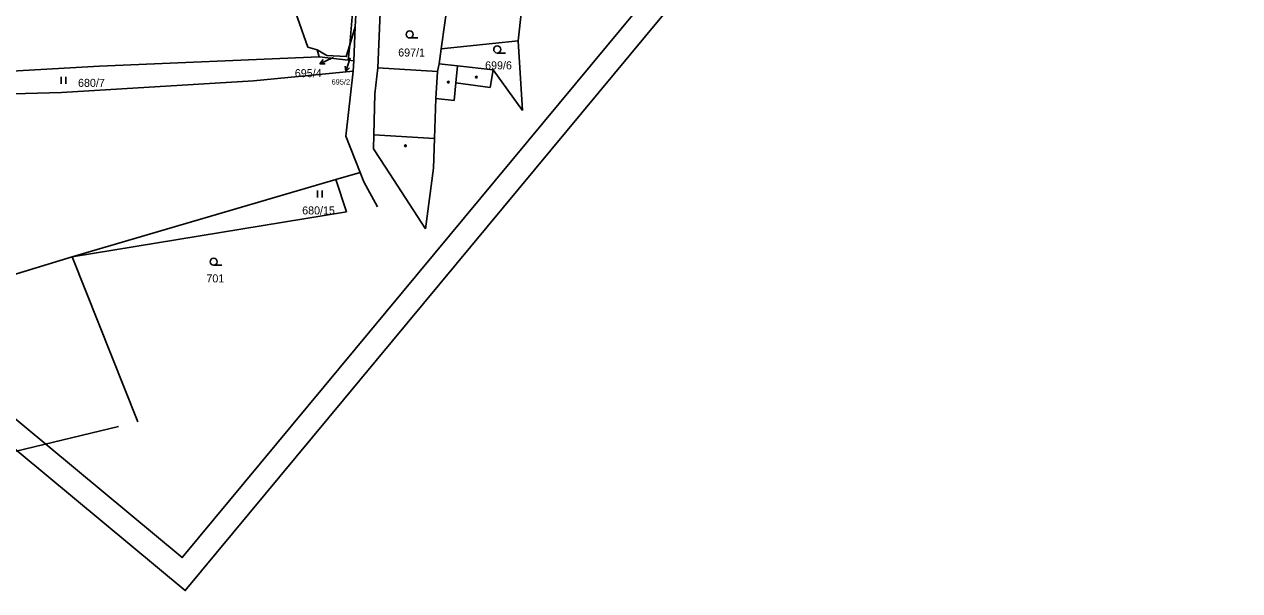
# Model space of a CAD drawing. Extents: x -738085 to -734306, y -1122197 to -1119753.
# Drawn here: x -737792.2 to -737534.1, y -1122100.7 to -1121980.5 of the extents above; entities that cross this region are included whole.
import ezdxf

# ---------------------------------------------------------------- set-up
doc = ezdxf.new("R2010")
doc.units = 0
for name, color, linetype in [('Hranice parcel', 7, 'Continuous'), ('Parcelní čísla', 7, 'Continuous'), ('Pop  PČ popisy', 7, 'Continuous'), ('Vnitřní kresba', 7, 'Continuous'), ('Vrstva 1', 7, 'Continuous'), ('Značky budov', 7, 'Continuous'), ('Značky kultur', 7, 'Continuous')]:
    doc.layers.add(name, color=color, linetype=linetype)

msp = doc.modelspace()

# ---------------------------------------------------------------- linework, layer by layer
at = {"layer": 'Hranice parcel'}
for p, q in [((-737723.1, -1121984.84), (-737719.99, -1121949.35)), ((-737719.99, -1121949.35), (-737721.96, -1121981)), ((-737698.78, -1121951.36), (-737703.7, -1121985.65)), ((-737715.8, -1121958.28), (-737717.16, -1121989.68)), ((-737686.62, -1121977.55), (-737687.29, -1121983.94)), ((-737721.96, -1121981), (-737723.1, -1121984.84)), ((-737722.26, -1121988.22), (-737721.96, -1121981)), ((-737729.62, -1121987.34), (-737730.02, -1121985.9)), ((-737723.1, -1121984.84), (-737723.45, -1121988.08)), ((-737704.12, -1121988.82), (-737703.7, -1121985.65)), ((-737703.7, -1121985.65), (-737687.29, -1121983.94)), ((-737687.29, -1121983.94), (-737686.38, -1121998.79)), ((-737723.45, -1121988.08), (-737729.62, -1121987.34)), ((-737723.45, -1121988.08), (-737722.26, -1121988.22)), ((-737722.4, -1121990.44), (-737722.26, -1121988.22)), ((-737704.42, -1121990.46), (-737717.16, -1121989.68)), ((-737704.12, -1121988.82), (-737704.42, -1121990.46)), ((-737726.05, -1122013.41), (-737782.09, -1122029.85)), ((-737720.88, -1122011.89), (-737726.05, -1122013.41)), ((-737726.05, -1122013.41), (-737723.75, -1122020.29)), ((-737723.75, -1122020.29), (-737782.09, -1122029.85)), ((-737782.09, -1122029.85), (-737768.13, -1122064.85)), ((-737824.02, -1122078.38), (-737772.19, -1122065.83))]:
    msp.add_line(p, q, dxfattribs=at)
for points in [[(-737737.66, -1121969.17), (-737731.99, -1121985.29), (-737730.02, -1121985.9)], [(-737729.62, -1121987.34), (-737776.28, -1121989.35), (-737809.96, -1121991.28), (-737851.63, -1121990.64), (-737874.79, -1121983.24), (-737896.76, -1121974.21)], [(-737730.02, -1121985.9), (-737727.93, -1121987.08), (-737723.83, -1121987.32), (-737723.1, -1121984.84)], [(-737853.32, -1121995.19), (-737814.9, -1121995.79), (-737784.29, -1121994.93), (-737743.54, -1121992.46), (-737722.4, -1121990.44)], [(-737720.88, -1122011.89), (-737723.91, -1122004.21), (-737722.4, -1121990.44)], [(-737717.16, -1121989.68), (-737717.74, -1121995.24), (-737717.96, -1122003.95), (-737718.03, -1122006.91), (-737715.5, -1122010.79), (-737706.99, -1122023.87)], [(-737706.99, -1122023.87), (-737705.27, -1122011.03), (-737705.09, -1122004.7), (-737704.84, -1121996.22), (-737704.42, -1121990.46)], [(-737686.38, -1121998.79), (-737692.64, -1121990.13), (-737700.22, -1121989.26), (-737704.12, -1121988.82)], [(-737717.19, -1122019.21), (-737720.07, -1122013.93), (-737720.88, -1122011.89)], [(-737782.09, -1122029.85), (-737804.12, -1122036.52), (-737829.18, -1122055.89)]]:
    msp.add_lwpolyline(points, dxfattribs=at)
at = {"layer": 'Pop  PČ popisy'}
for p, q in [((-737726.74, -1121987.56), (-737729.46, -1121988.83)), ((-737729.46, -1121988.83), (-737728.76, -1121987.95)), ((-737726.55, -1121987.48), (-737726.74, -1121987.56)), ((-737722.98, -1121987.61), (-737723.91, -1121990.46)), ((-737729.46, -1121988.83), (-737728.34, -1121988.86)), ((-737723.91, -1121990.46), (-737724.07, -1121989.36)), ((-737723.91, -1121990.46), (-737723.12, -1121989.67))]:
    msp.add_line(p, q, dxfattribs=at)
at = {"layer": 'Vnitřní kresba'}
for p, q in [((-737700.22, -1121989.26), (-737700.55, -1121992.92)), ((-737693.27, -1121993.91), (-737692.64, -1121990.13)), ((-737700.55, -1121992.92), (-737700.88, -1121996.65)), ((-737700.55, -1121992.92), (-737693.27, -1121993.91)), ((-737704.84, -1121996.22), (-737700.88, -1121996.65)), ((-737717.96, -1122003.95), (-737705.09, -1122004.7))]:
    msp.add_line(p, q, dxfattribs=at)
at = {"layer": 'Vrstva 1'}
for points in [[(-737449.7, -1121264.8), (-737986.48, -1121910.91), (-737758.04, -1122100.69), (-737221.26, -1121454.59)], [(-737979.44, -1121910.26), (-737449.05, -1121271.84), (-737228.3, -1121455.24), (-737758.69, -1122093.65)]]:
    msp.add_lwpolyline(points, close=True, dxfattribs=at)
at = {"layer": 'Značky budov'}
for centre in [(-737702.17, -1121992.74), (-737696.22, -1121991.67), (-737711.26, -1122006.25)]:
    msp.add_circle(centre, 0.175, dxfattribs=at)
at = {"layer": 'Značky kultur'}
for p, q in [((-737710.36, -1121983.37), (-737708.61, -1121983.37)), ((-737691.77, -1121986.56), (-737690.02, -1121986.56)), ((-737784.39, -1121993.12), (-737784.39, -1121991.62)), ((-737783.39, -1121993.12), (-737783.39, -1121991.62)), ((-737729.94, -1122017.22), (-737729.94, -1122015.72)), ((-737728.94, -1122017.22), (-737728.94, -1122015.72)), ((-737752, -1122031.61), (-737750.25, -1122031.61))]:
    msp.add_line(p, q, dxfattribs=at)
for centre in [(-737710.36, -1121982.62), (-737691.77, -1121985.81), (-737752, -1122030.86)]:
    msp.add_circle(centre, 0.75, dxfattribs=at)

# ---------------------------------------------------------------- texts
at = {"layer": 'Parcelní čísla'}
for s, height, p in [('697/1', 1.7, (-737712.8, -1121987.3)), ('699/6', 1.7, (-737694.34, -1121990.03)), ('695/4', 1.7, (-737734.76, -1121991.68)), ('680/7', 1.7, (-737780.81, -1121993.74)), ('695/2', 1.139, (-737726.96, -1121993.26)), ('680/15', 1.7, (-737733.2, -1122020.82)), ('701', 1.7, (-737753.54, -1122035.25))]:
    msp.add_text(s, height=height, dxfattribs=at).set_placement(p)

doc.saveas('drawing.dxf')
